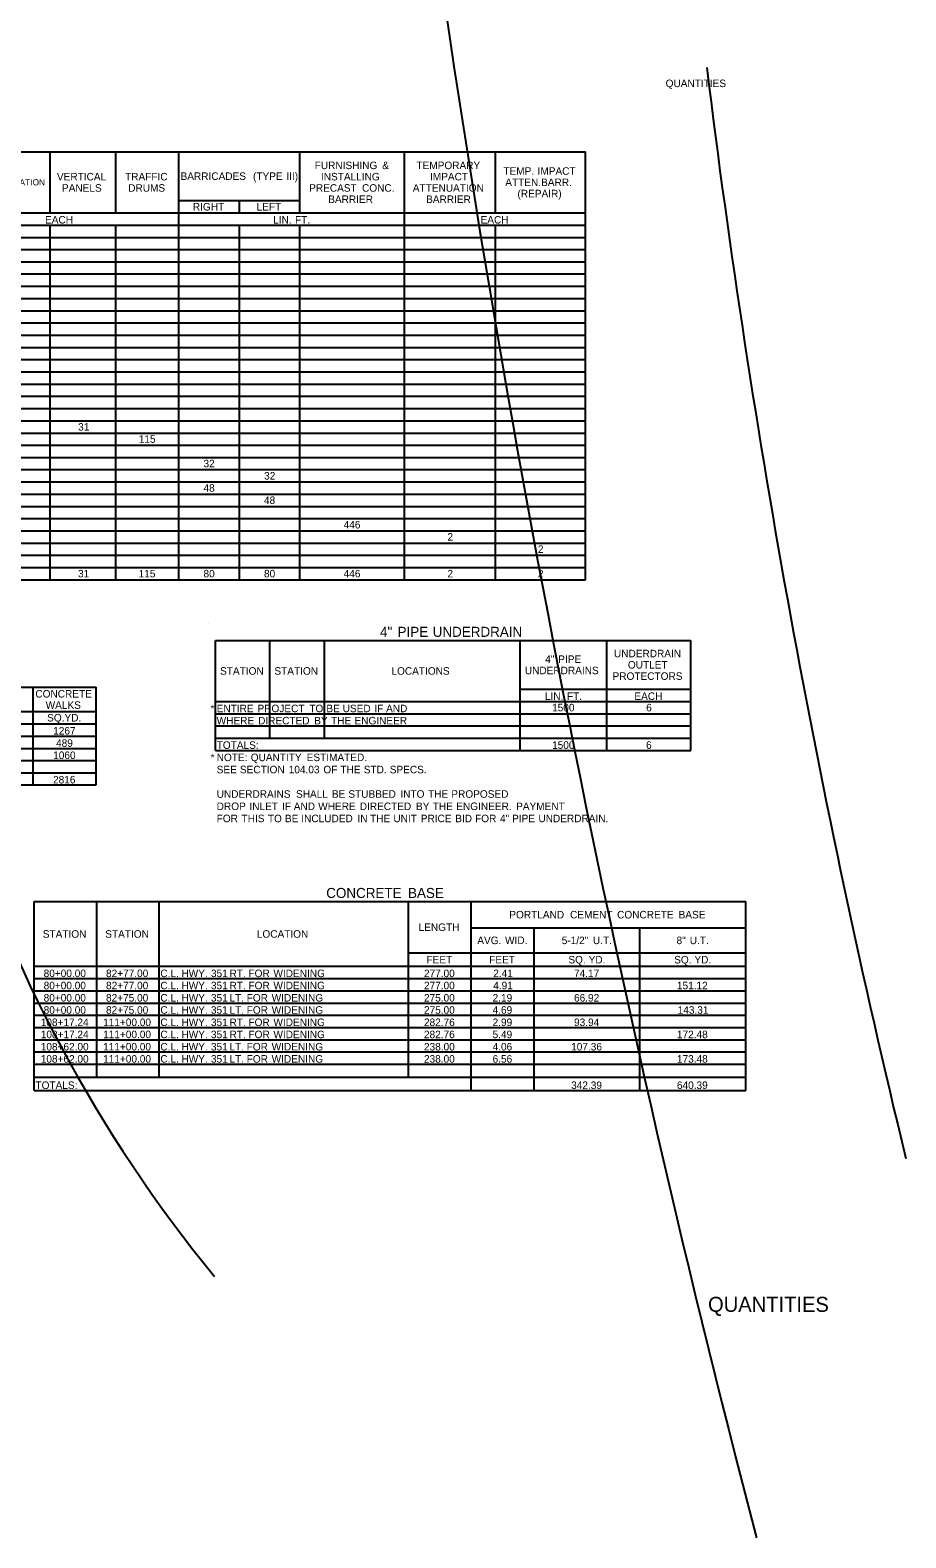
# Model space of a CAD drawing. Extents: x 1197542 to 1207068, y 230488 to 237324.
# Drawn here: x 1198833 to 1199531, y 231549 to 232751 of the extents above; entities that cross this region are included whole.
import ezdxf

# ---------------------------------------------------------------- set-up
doc = ezdxf.new("R2010")
doc.units = 0
for name, color, linetype in [('Default', 7, 'Continuous'), ('R_Annotation', 7, 'Continuous'), ('R_Border', 7, 'Continuous'), ('R_Proposed Road_Shoulder', 7, 'Continuous')]:
    doc.layers.add(name, color=color, linetype=linetype)

msp = doc.modelspace()

# ---------------------------------------------------------------- linework, layer by layer
at = {"layer": 'Default'}
for p, q in [((1198084.5, 232654.5), (1199276, 232654.5)), ((1198849.4, 232605.7), (1198849.4, 232654.5)), ((1198901.6, 232605.7), (1198901.6, 232654.5)), ((1198951.8, 232313.2), (1198951.8, 232654.5)), ((1199048.3, 232605.7), (1199048.3, 232654.5)), ((1199131.7, 232313.2), (1199131.7, 232654.5)), ((1199204.3, 232605.7), (1199204.3, 232654.5)), ((1199276, 232313.2), (1199276, 232654.5)), ((1198951.8, 232615.5), (1199048.3, 232615.5)), ((1199000.1, 232605.7), (1199000.1, 232615.5)), ((1199000.1, 232605.7), (1199000.1, 232615.5)), ((1198661.2, 232605.7), (1199276, 232605.7)), ((1198951.8, 232605.7), (1199000.1, 232605.7)), ((1198951.8, 232313.2), (1198951.8, 232605.7)), ((1199000.1, 232605.7), (1199276, 232605.7)), ((1199131.7, 232313.2), (1199131.7, 232605.7)), ((1198084.5, 232596), (1199276, 232596)), ((1198603.2, 232596), (1199276, 232596)), ((1198849.4, 232313.2), (1198849.4, 232596)), ((1198849.4, 232313.2), (1198849.4, 232596)), ((1198901.6, 232313.2), (1198901.6, 232596)), ((1198901.6, 232313.2), (1198901.6, 232596)), ((1199000.1, 232323), (1199000.1, 232596)), ((1199000.1, 232313.2), (1199000.1, 232596)), ((1199048.3, 232323), (1199048.3, 232596)), ((1199048.3, 232313.2), (1199048.3, 232596)), ((1199204.3, 232362), (1199204.3, 232596)), ((1199204.3, 232313.2), (1199204.3, 232596)), ((1198084.5, 232586.2), (1199276, 232586.2)), ((1198084.5, 232576.5), (1199276, 232576.5)), ((1198084.5, 232566.7), (1199276, 232566.7)), ((1198084.5, 232557), (1199276, 232557)), ((1198084.5, 232547.2), (1199276, 232547.2)), ((1198084.5, 232537.5), (1199276, 232537.5)), ((1198084.5, 232527.7), (1199276, 232527.7)), ((1198084.5, 232518), (1199276, 232518)), ((1198084.5, 232508.2), (1199276, 232508.2)), ((1198084.5, 232498.5), (1199276, 232498.5)), ((1198084.5, 232488.7), (1199276, 232488.7)), ((1198084.5, 232479), (1199276, 232479)), ((1198084.5, 232469.2), (1199276, 232469.2)), ((1198084.5, 232459.5), (1199276, 232459.5)), ((1198084.5, 232449.7), (1199276, 232449.7)), ((1198084.5, 232440), (1199276, 232440)), ((1198084.5, 232430.2), (1199276, 232430.2)), ((1198084.5, 232420.5), (1199276, 232420.5)), ((1198084.5, 232410.7), (1199276, 232410.7)), ((1198084.5, 232401), (1199276, 232401)), ((1198084.5, 232391.2), (1199276, 232391.2)), ((1198084.5, 232381.5), (1199276, 232381.5)), ((1198084.5, 232371.7), (1199276, 232371.7)), ((1198084.5, 232362), (1199276, 232362)), ((1198134.7, 232352.2), (1199276, 232352.2)), ((1199204.3, 232313.2), (1199204.3, 232352.2)), ((1198084.5, 232342.5), (1199276, 232342.5)), ((1198084.5, 232332.7), (1199276, 232332.7)), ((1198084.5, 232323), (1199276, 232323)), ((1198084.5, 232313.2), (1199276, 232313.2)), ((1198975.2, 232278.6), (1198975.2, 232278.6)), ((1198981, 232264.9), (1199359.8, 232264.9)), ((1198981, 232177.2), (1198981, 232264.9)), ((1198981, 232177.2), (1198981, 232264.9)), ((1199024.4, 232186.9), (1199024.4, 232264.9)), ((1199067.8, 232186.9), (1199067.8, 232264.9)), ((1199223.8, 232177.2), (1199223.8, 232264.9)), ((1199293, 232177.2), (1199293, 232264.9)), ((1199359.8, 232177.2), (1199359.8, 232264.9)), ((1199359.8, 232177.2), (1199359.8, 232264.9)), ((1198529.1, 232227.6), (1198885.9, 232227.6)), ((1198835.7, 232149.6), (1198835.7, 232227.6)), ((1198885.9, 232149.6), (1198885.9, 232227.6)), ((1198885.9, 232149.6), (1198885.9, 232227.6)), ((1199223.8, 232225.9), (1199359.8, 232225.9)), ((1198785.5, 232208.1), (1198885.9, 232208.1)), ((1198835.7, 232149.6), (1198835.7, 232208.1)), ((1198981, 232216.2), (1199293, 232216.2)), ((1198981, 232216.2), (1199359.8, 232216.2)), ((1198981, 232206.4), (1199359.8, 232206.4)), ((1199024.4, 232186.9), (1199024.4, 232216.2)), ((1199067.8, 232186.9), (1199067.8, 232216.2)), ((1199223.8, 232177.2), (1199223.8, 232216.2)), ((1199293, 232216.2), (1199359.8, 232216.2)), ((1198529.1, 232198.3), (1198835.7, 232198.3)), ((1198785.5, 232198.3), (1198835.7, 232198.3)), ((1198835.7, 232198.3), (1198885.9, 232198.3)), ((1198981, 232196.7), (1199359.8, 232196.7)), ((1198529.1, 232188.6), (1198885.9, 232188.6)), ((1198981, 232186.9), (1199359.8, 232186.9)), ((1198529.1, 232178.8), (1198885.9, 232178.8)), ((1198529.1, 232169.1), (1198885.9, 232169.1)), ((1198981, 232177.2), (1199359.8, 232177.2)), ((1198529.1, 232159.3), (1198885.9, 232159.3)), ((1198835.7, 232159.3), (1198885.9, 232159.3)), ((1198529.1, 232149.6), (1198885.9, 232149.6)), ((1198836.6, 232056.6), (1199403.6, 232056.6)), ((1198836.6, 231906), (1198836.6, 232056.6)), ((1198836.6, 231906), (1198836.6, 232056.6)), ((1198886.4, 231916.7), (1198886.4, 232056.6)), ((1198936.1, 231916.7), (1198936.1, 232056.6)), ((1199135, 231916.7), (1199135, 232056.6)), ((1199184.7, 231906), (1199184.7, 232056.6)), ((1199403.6, 231906), (1199403.6, 232056.6)), ((1199184.7, 232035.7), (1199403.6, 232035.7)), ((1199234.9, 231906), (1199234.9, 232035.7)), ((1199319.3, 231906), (1199319.3, 232035.7)), ((1199135, 232015.7), (1199403.6, 232015.7)), ((1199184.7, 232005), (1199184.7, 232015.7)), ((1198836.6, 232005), (1199184.7, 232005)), ((1198836.6, 232005), (1199135, 232005)), ((1199135, 232005), (1199403.6, 232005)), ((1199234.9, 232005), (1199403.6, 232005)), ((1198836.6, 231995.2), (1199403.6, 231995.2)), ((1199234.9, 231995.2), (1199403.6, 231995.2)), ((1198836.6, 231985.5), (1199403.6, 231985.5)), ((1199319.3, 231985.5), (1199403.6, 231985.5)), ((1198836.6, 231975.7), (1199403.6, 231975.7)), ((1198836.6, 231966), (1199403.6, 231966)), ((1199319.3, 231975.7), (1199403.6, 231975.7)), ((1199319.3, 231966), (1199403.6, 231966)), ((1198836.6, 231956.2), (1199403.6, 231956.2)), ((1199234.9, 231956.2), (1199403.6, 231956.2)), ((1198836.6, 231946.5), (1199403.6, 231946.5)), ((1199234.9, 231946.5), (1199403.6, 231946.5)), ((1198836.6, 231936.7), (1199403.6, 231936.7)), ((1199319.3, 231936.7), (1199403.6, 231936.7)), ((1198836.6, 231927), (1199403.6, 231927)), ((1198836.6, 231916.7), (1199403.6, 231916.7)), ((1199184.7, 231906), (1199184.7, 231916.7)), ((1199319.3, 231927), (1199403.6, 231927)), ((1198836.6, 231906), (1199403.6, 231906))]:
    msp.add_line(p, q, dxfattribs=at)
at = {"layer": 'R_Proposed Road_Shoulder'}
for centre, radius, start, end in [((1210501.1, 234438.6), 11459.2, 187.50313, 194.60389), ((1206954.6, 233655.7), 7639.4, 187.02338, 193.65746), ((1199867.7, 232482.6), 1145.9, 197.2567, 219.2476)]:
    msp.add_arc(centre, radius, start, end, dxfattribs=at)

# ---------------------------------------------------------------- texts
at = {"layer": 'Default'}
for s, height, p in [('BARRICADES', 6, (1198953.2, 232632)), (' (TYPE', 6, (1199008.7, 232632)), (' III)', 6, (1199035.3, 232632)), ('FURNISHING', 6, (1199060.1, 232640.6)), (' &', 6, (1199111.7, 232640.6)), ('TEMPORARY', 6, (1199141.2, 232640.6)), ('TEMP.', 6, (1199210.5, 232636.1)), (' IMPACT', 6, (1199235.5, 232636.1)), (' INFORMATION', 5, (1198796.6, 232627.6)), ('VERTICAL', 6, (1198854.7, 232631.6)), ('PANELS', 6, (1198858.7, 232622.6)), ('TRAFFIC', 6, (1198909, 232631.6)), ('DRUMS', 6, (1198911.5, 232622.6)), ('PRECAST', 6, (1199055.7, 232622.6)), ('INSTALLING', 6, (1199065.1, 232631.6)), (' CONC.', 6, (1199095.6, 232622.6)), ('ATTENUATION', 6, (1199138.3, 232622.6)), ('IMPACT', 6, (1199152, 232631.6)), ('ATTEN.BARR.', 6, (1199212, 232627.1)), ('BARRIER', 6, (1199070.9, 232613.6)), ('BARRIER', 6, (1199148.9, 232613.6)), ('(REPAIR)', 6, (1199221.7, 232618.1)), ('EACH', 6, (1198845.2, 232597.2)), ('RIGHT', 6, (1198963, 232607.6)), ('LEFT', 6, (1199013.8, 232607.6)), ('LIN.', 6, (1199027, 232597.2)), (' FT.', 6, (1199042.2, 232597.2)), ('EACH', 6, (1199192.3, 232597.2)), ('31', 6, (1198871.6, 232432.1)), ('115', 6, (1198919.9, 232422.4)), ('32', 6, (1198971.5, 232402.9)), ('32', 6, (1199019.8, 232393.1)), ('48', 6, (1198971.5, 232383.4)), ('48', 6, (1199019.7, 232373.6)), ('446', 6, (1199083.2, 232354.1)), ('2', 6, (1199165.9, 232344.4)), ('2', 6, (1199238, 232334.6)), ('31', 6, (1198871.5, 232315.1)), ('115', 6, (1198919.8, 232315.1)), ('80', 6, (1198971.5, 232315.1)), ('80', 6, (1199019.7, 232315.1)), ('446', 6, (1199083.2, 232315.1)), ('2', 6, (1199165.9, 232315.1)), ('2', 6, (1199238, 232315.1)), ('4"', 8, (1199112.2, 232267.7)), (' PIPE', 8, (1199123.2, 232267.7)), (' UNDERDRAIN', 8, (1199151.2, 232267.7)), ('UNDERDRAIN', 6, (1199298.6, 232251.4)), ('STATION', 6, (1198984.7, 232237.5)), ('STATION', 6, (1199028, 232237.5)), ('LOCATIONS', 6, (1199121.3, 232237.5)), ('UNDERDRAINS', 6, (1199227.6, 232237.9)), ('4"', 6, (1199243.8, 232246.9)), (' PIPE', 6, (1199252, 232246.9)), ('OUTLET', 6, (1199309.7, 232242.4)), ('PROTECTORS', 6, (1199297.5, 232233.4)), ('CONCRETE', 6, (1198837.5, 232219.3)), ('LIN.', 6, (1199243.6, 232217.4)), (' FT.', 6, (1199258.9, 232217.4)), ('EACH', 6, (1199314.9, 232217.4)), ('WALKS', 6, (1198845.7, 232210.3)), ('SQ.YD.', 6, (1198846.9, 232200.2)), ('*', 6, (1198977.1, 232207.6)), ('ENTIRE', 6, (1198982, 232207.6)), (' PROJECT', 6, (1199012.3, 232207.6)), (' TO', 6, (1199053.6, 232207.6)), (' BE', 6, (1199067.2, 232207.6)), (' USED', 6, (1199080.2, 232207.6)), (' IF', 6, (1199105.4, 232207.6)), (' AND', 6, (1199114.8, 232207.6)), ('1500', 6, (1199249.3, 232208.3)), ('6', 6, (1199324.3, 232208.3)), ('1267', 6, (1198851.7, 232189.8)), ('WHERE', 6, (1198982, 232197.9)), (' DIRECTED', 6, (1199012.8, 232197.9)), (' BY', 6, (1199057.5, 232197.9)), (' THE', 6, (1199070.9, 232197.9)), (' ENGINEER', 6, (1199089.6, 232197.9)), ('489', 6, (1198854, 232180)), ('TOTALS:', 6, (1198982, 232178.4)), ('1500', 6, (1199249.3, 232178.4)), ('6', 6, (1199324.2, 232178.4)), ('1060', 6, (1198851.7, 232170.3)), ('*', 6, (1198977.1, 232168.6)), ('NOTE:', 6, (1198982, 232168.6)), (' QUANTITY', 6, (1199006.9, 232168.6)), (' ESTIMATED.', 6, (1199051.5, 232168.6)), ('SEE', 6, (1198982, 232158.9)), (' SECTION', 6, (1198998.3, 232158.9)), (' 104.03', 6, (1199037.2, 232158.9)), (' OF', 6, (1199064.8, 232158.9)), (' THE', 6, (1199078.4, 232158.9)), (' STD.', 6, (1199097, 232158.9)), (' SPECS.', 6, (1199117.7, 232158.9)), ('2816', 6, (1198851.6, 232150.8)), ('UNDERDRAINS', 6, (1198982, 232139.4)), (' SHALL', 6, (1199043, 232139.4)), (' BE', 6, (1199071.6, 232139.4)), (' STUBBED', 6, (1199084.7, 232139.4)), (' INTO', 6, (1199126.2, 232139.4)), (' THE', 6, (1199148.2, 232139.4)), (' PROPOSED', 6, (1199166.8, 232139.4)), ('DROP', 6, (1198982, 232129.6)), (' INLET', 6, (1199005.9, 232129.6)), (' IF', 6, (1199031.8, 232129.6)), (' AND', 6, (1199041.2, 232129.6)), (' WHERE', 6, (1199060.7, 232129.6)), (' DIRECTED', 6, (1199093.8, 232129.6)), (' BY', 6, (1199138.6, 232129.6)), (' THE', 6, (1199152, 232129.6)), (' ENGINEER.', 6, (1199170.7, 232129.6)), (' PAYMENT', 6, (1199218.4, 232129.6)), ('FOR', 6, (1198982, 232119.9)), (' THIS', 6, (1198999.6, 232119.9)), (' TO', 6, (1199020.6, 232119.9)), (' BE', 6, (1199034.2, 232119.9)), (' INCLUDED', 6, (1199047.2, 232119.9)), (' IN', 6, (1199092, 232119.9)), (' THE', 6, (1199102, 232119.9)), (' UNIT', 6, (1199120.6, 232119.9)), (' PRICE', 6, (1199142.4, 232119.9)), (' BID', 6, (1199169.9, 232119.9)), (' FOR', 6, (1199185.7, 232119.9)), (' 4"', 6, (1199205.6, 232119.9)), (' PIPE', 6, (1199215.2, 232119.9)), (' UNDERDRAIN.', 6, (1199236.2, 232119.9)), ('CONCRETE', 8, (1199069.3, 232059.5)), (' BASE', 8, (1199131.5, 232059.5)), ('PORTLAND', 6, (1199215.2, 232043.2)), (' CEMENT', 6, (1199261.4, 232043.2)), (' CONCRETE', 6, (1199298.9, 232043.2)), (' BASE', 6, (1199347.9, 232043.2)), ('LENGTH', 6, (1199142.9, 232033.2)), ('STATION', 6, (1198843.4, 232027.8)), ('STATION', 6, (1198893.2, 232027.8)), ('LOCATION', 6, (1199014, 232027.8)), ('AVG.', 6, (1199189.7, 232022.7)), (' WID.', 6, (1199209.6, 232022.7)), ('5-1/2"', 6, (1199257, 232022.7)), (' U.T.', 6, (1199279.6, 232022.7)), ('8"', 6, (1199348.5, 232022.7)), (' U.T.', 6, (1199356.8, 232022.7)), ('FEET', 6, (1199149.2, 232007.3)), ('FEET', 6, (1199199.2, 232007.3)), ('SQ.', 6, (1199262.3, 232007.3)), (' YD.', 6, (1199276.2, 232007.3)), ('SQ.', 6, (1199346.6, 232007.3)), (' YD.', 6, (1199360.5, 232007.3)), ('80+00.00', 6, (1198844.1, 231996.4)), ('82+77.00', 6, (1198893.8, 231996.4)), ('C.L.', 6, (1198937.1, 231996.4)), (' HWY.', 6, (1198951.7, 231996.4)), (' 351', 6, (1198975.2, 231996.4)), (' RT.', 6, (1198990, 231996.4)), (' FOR', 6, (1199005.1, 231996.4)), (' WIDENING', 6, (1199025, 231996.4)), ('277.00', 6, (1199147.2, 231996.4)), ('2.41', 6, (1199202.4, 231996.4)), ('74.17', 6, (1199266.8, 231996.4)), ('80+00.00', 6, (1198844.1, 231986.7)), ('82+77.00', 6, (1198893.8, 231986.7)), ('C.L.', 6, (1198937.1, 231986.7)), (' HWY.', 6, (1198951.7, 231986.7)), (' 351', 6, (1198975.2, 231986.7)), (' RT.', 6, (1198990, 231986.7)), (' FOR', 6, (1199005.1, 231986.7)), (' WIDENING', 6, (1199025, 231986.7)), ('277.00', 6, (1199147.2, 231986.7)), ('4.91', 6, (1199202.4, 231986.7)), ('151.12', 6, (1199348.8, 231986.7)), ('80+00.00', 6, (1198844.1, 231976.9)), ('82+75.00', 6, (1198893.8, 231976.9)), ('C.L.', 6, (1198937.1, 231976.9)), (' HWY.', 6, (1198951.7, 231976.9)), (' 351', 6, (1198975.2, 231976.9)), (' LT.', 6, (1198990, 231976.9)), (' FOR', 6, (1199003.7, 231976.9)), (' WIDENING', 6, (1199023.6, 231976.9)), ('275.00', 6, (1199147.2, 231976.9)), ('2.19', 6, (1199201.9, 231976.9)), ('66.92', 6, (1199266.8, 231976.9)), ('80+00.00', 6, (1198844.1, 231967.2)), ('82+75.00', 6, (1198893.8, 231967.2)), ('C.L.', 6, (1198937.1, 231967.2)), (' HWY.', 6, (1198951.7, 231967.2)), (' 351', 6, (1198975.2, 231967.2)), (' LT.', 6, (1198990, 231967.2)), (' FOR', 6, (1199003.7, 231967.2)), (' WIDENING', 6, (1199023.6, 231967.2)), ('275.00', 6, (1199147.2, 231967.2)), ('4.69', 6, (1199201.9, 231967.2)), ('143.31', 6, (1199349.4, 231967.2)), ('108+17.24', 6, (1198841.8, 231957.4)), ('108+17.24', 6, (1198841.8, 231947.7)), ('111+00.00', 6, (1198891.5, 231957.4)), ('111+00.00', 6, (1198891.5, 231947.7)), ('C.L.', 6, (1198937.1, 231957.4)), ('C.L.', 6, (1198937.1, 231947.7)), (' HWY.', 6, (1198951.7, 231957.4)), (' HWY.', 6, (1198951.7, 231947.7)), (' 351', 6, (1198975.2, 231957.4)), (' 351', 6, (1198975.2, 231947.7)), (' RT.', 6, (1198990, 231957.4)), (' RT.', 6, (1198990, 231947.7)), (' FOR', 6, (1199005.1, 231957.4)), (' FOR', 6, (1199005.1, 231947.7)), (' WIDENING', 6, (1199025, 231957.4)), (' WIDENING', 6, (1199025, 231947.7)), ('282.76', 6, (1199147.2, 231957.4)), ('282.76', 6, (1199147.2, 231947.7)), ('5.49', 6, (1199201.9, 231947.7)), ('2.99', 6, (1199201.9, 231957.4)), ('93.94', 6, (1199266.8, 231957.4)), ('172.48', 6, (1199348.8, 231947.7)), ('108+62.00', 6, (1198841.8, 231937.9)), ('111+00.00', 6, (1198891.5, 231937.9)), ('C.L.', 6, (1198937.1, 231937.9)), (' HWY.', 6, (1198951.7, 231937.9)), (' 351', 6, (1198975.2, 231937.9)), (' LT.', 6, (1198990, 231937.9)), (' FOR', 6, (1199003.7, 231937.9)), (' WIDENING', 6, (1199023.6, 231937.9)), ('238.00', 6, (1199147.2, 231937.9)), ('4.06', 6, (1199201.9, 231937.9)), ('107.36', 6, (1199264.5, 231937.9)), ('108+62.00', 6, (1198841.8, 231928.2)), ('111+00.00', 6, (1198891.5, 231928.2)), ('C.L.', 6, (1198937.1, 231928.2)), (' HWY.', 6, (1198951.7, 231928.2)), (' 351', 6, (1198975.2, 231928.2)), (' LT.', 6, (1198990, 231928.2)), (' FOR', 6, (1199003.7, 231928.2)), (' WIDENING', 6, (1199023.6, 231928.2)), ('238.00', 6, (1199147.2, 231928.2)), ('6.56', 6, (1199201.9, 231928.2)), ('173.48', 6, (1199348.8, 231928.2)), ('TOTALS:', 6, (1198837.6, 231907.2)), ('342.39', 6, (1199264.5, 231907.2)), ('640.39', 6, (1199348.8, 231907.2))]:
    msp.add_text(s, height=height, dxfattribs=at).set_placement(p)
at = {"layer": 'R_Annotation'}
msp.add_text('QUANTITIES', height=12, rotation=360, dxfattribs=at).set_placement((1199373.6, 231729.5))
at = {"layer": 'R_Border'}
msp.add_text('QUANTITIES', height=6, rotation=360, dxfattribs=at).set_placement((1199339.8, 232706))

doc.saveas('drawing.dxf')
